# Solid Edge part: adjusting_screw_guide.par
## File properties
Title: Adjusting screw guide
Author: Robert a Rhodes jr
Template: Normal.par
Last saved by: Cadcim
Revision: 3
Application: Solid Edge
Accuracy: 0.99
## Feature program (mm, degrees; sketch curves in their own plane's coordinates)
sketch for "unnamed Protrusion 1" plane through (0, 0, 0) normal (0, -1, 0) x-axis (1, 0, 0)
  circle centre (0, 0) radius 7.9375
extrude "unnamed Protrusion 1" add finite 63.5 along +normal
sketch for "ExtrudedProtrusion_2" plane through (0, -63.5, 0) normal (0, -1, 0) x-axis (1, 0, 0)
  circle centre (0, 0) radius 6.3119
extrude "ExtrudedProtrusion_2" add finite 76.2 along +normal
chamfer "Chamfer_1" setback 1.5748
sketch for "ExtrudedCutout_1" plane through (0, 0, 0) normal (0, 0, 1) x-axis (1, 0, 0)
  line (1.1811, 0) -> (1.1811, -4.7498)
  line (1.1811, -4.7498) -> (-1.1811, -4.7498)
  line (-1.1811, -4.7498) -> (-1.1811, 0)
  line (-1.1811, 0) -> (1.1811, 0)
extrude "ExtrudedCutout_1" cut finite 101.6 symmetric
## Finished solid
Body 1: solid body, 10 faces, 16 edges, 8 vertices.
  Faces by surface: plane 7, cylinder 2, cone 1
  Edges by curve: circle 8, line 8
Bounding box of the edges (mm): 15.875 x 139.700 x 15.875, from (-7.9375, -139.7, -7.9375) to (7.9375, 0, 7.9375).
Cylindrical faces by radius (mm): R6.3119 x1, R7.9375 x1
Conical faces (half-angle, radius in mm at the cone's reference point): 45 deg R6.3119 x1
Planar faces by outward normal: +x 1, +y 3, -x 1, -y 2
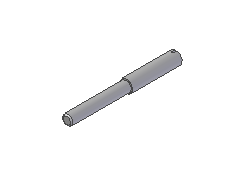
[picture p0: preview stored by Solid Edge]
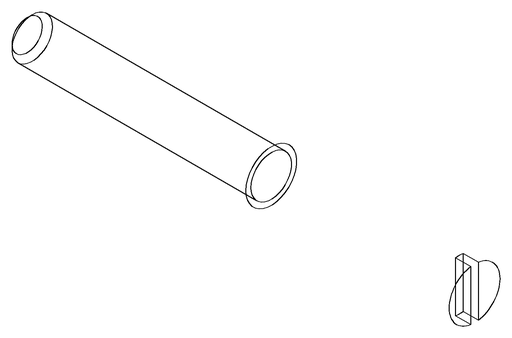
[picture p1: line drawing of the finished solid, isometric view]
